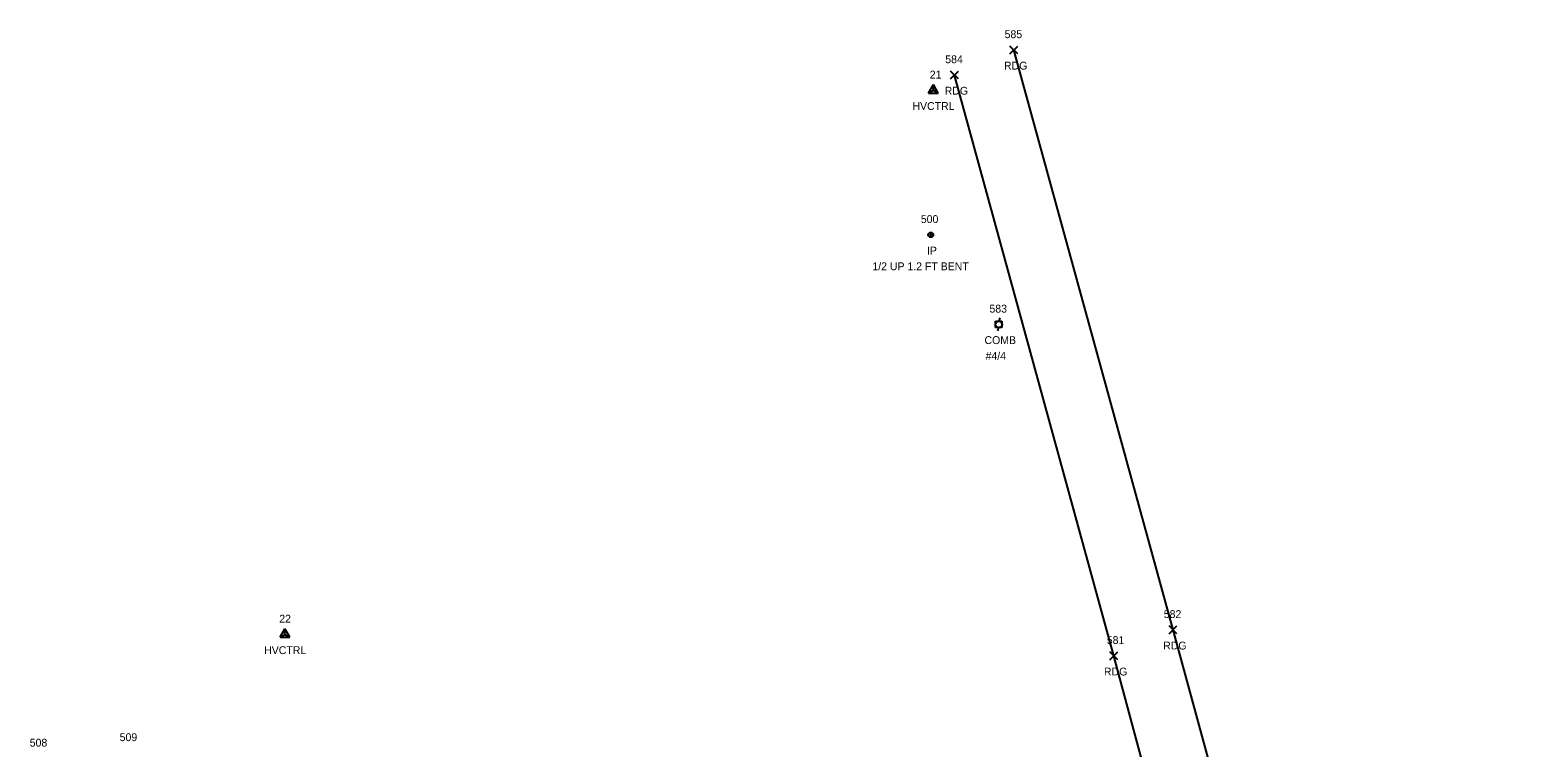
# Model space of a CAD drawing. Extents: x 1845178 to 1850791, y 714586 to 722436.
# Drawn here: x 1850338.3 to 1850721.9, y 716795.6 to 716978.2 of the extents above; entities that cross this region are included whole.
import ezdxf

# ---------------------------------------------------------------- set-up
doc = ezdxf.new("R2010")
doc.units = 0
for name, color, linetype in [('C_A', 7, 'Continuous'), ('C_I', 7, 'Continuous'), ('CPSM', 7, 'Continuous'), ('M_A', 7, 'Continuous'), ('M_C', 7, 'Continuous'), ('M_I', 7, 'Continuous'), ('MPIR', 7, 'Continuous'), ('P_A', 7, 'Continuous'), ('P_I', 7, 'Continuous'), ('P_TIC', 7, 'Continuous'), ('PEU', 7, 'Continuous'), ('R_I', 7, 'Continuous'), ('U_A', 7, 'Continuous'), ('U_C', 7, 'Continuous'), ('U_I', 7, 'Continuous'), ('UP', 7, 'Continuous')]:
    doc.layers.add(name, color=color, linetype=linetype)

msp = doc.modelspace()

# ---------------------------------------------------------------- linework, layer by layer
at = {"layer": 'CPSM'}
for p, q in [((1850566.84, 716962.13), (1850568.09, 716964.29)), ((1850566.84, 716962.13), (1850568.09, 716962.85)), ((1850569.34, 716962.13), (1850568.09, 716964.29)), ((1850568.09, 716962.85), (1850568.09, 716964.29)), ((1850568.09, 716962.85), (1850568.09, 716962.85)), ((1850568.09, 716962.85), (1850569.34, 716962.13)), ((1850566.84, 716962.13), (1850569.34, 716962.13)), ((1850401.87, 716823.71), (1850403.12, 716825.88)), ((1850401.87, 716823.71), (1850403.12, 716824.43)), ((1850404.37, 716823.71), (1850403.12, 716825.88)), ((1850403.12, 716824.43), (1850403.12, 716825.88)), ((1850403.12, 716824.43), (1850403.12, 716824.43)), ((1850403.12, 716824.43), (1850404.37, 716823.71)), ((1850401.87, 716823.71), (1850404.37, 716823.71))]:
    msp.add_line(p, q, dxfattribs=at)
at = {"layer": 'MPIR'}
for radius in [0.625, 0.0833]:
    msp.add_circle((1850567.44, 716926.08), radius, dxfattribs=at)
at = {"layer": 'P_TIC'}
for points in [[(1850587.58, 716972.12), (1850589.58, 716974.12)], [(1850589.58, 716972.12), (1850587.58, 716974.12)], [(1850572.49, 716965.74), (1850574.49, 716967.74)], [(1850574.49, 716965.74), (1850572.49, 716967.74)], [(1850628.08, 716824.6), (1850630.08, 716826.6)], [(1850630.08, 716824.6), (1850628.08, 716826.6)], [(1850613.03, 716817.99), (1850615.03, 716819.99)], [(1850615.03, 716817.99), (1850613.03, 716819.99)]]:
    msp.add_lwpolyline(points, dxfattribs=at)
at = {"layer": 'PEU'}
for points in [[(1850721.91, 716490.1), (1850702.6, 716555.29), (1850682.65, 716631.73), (1850661.37, 716707.44), (1850629.08, 716825.6), (1850588.58, 716973.12)], [(1850650.3, 716680.85), (1850644.64, 716705.31), (1850614.03, 716818.99), (1850573.49, 716966.74)]]:
    msp.add_lwpolyline(points, dxfattribs=at)
at = {"layer": 'UP'}
for p, q in [((1850584.98, 716904.97), (1850584.73, 716904.13)), ((1850583.89, 716902.47), (1850583.89, 716904.13)), ((1850583.89, 716904.13), (1850585.56, 716904.13)), ((1850585.56, 716902.47), (1850583.89, 716902.47)), ((1850584.48, 716901.63), (1850584.73, 716902.47)), ((1850584.73, 716903.3), (1850584.73, 716903.3)), ((1850585.56, 716904.13), (1850585.56, 716902.47))]:
    msp.add_line(p, q, dxfattribs=at)
msp.add_circle((1850584.73, 716903.3), 0.833, dxfattribs=at)

# ---------------------------------------------------------------- texts
at = {"layer": 'C_A'}
for p in [(1850562.78, 716957.85), (1850397.82, 716819.43)]:
    msp.add_text('HVCTRL', height=2, dxfattribs=at).set_placement(p)
at = {"layer": 'C_I'}
for s, p in [('21', (1850567.19, 716965.85)), ('22', (1850401.66, 716827.43))]:
    msp.add_text(s, height=2, dxfattribs=at).set_placement(p)
at = {"layer": 'M_A'}
msp.add_text('IP', height=2, dxfattribs=at).set_placement((1850566.48, 716921.08))
at = {"layer": 'M_C'}
msp.add_text('1/2 UP 1.2 FT BENT', height=2, dxfattribs=at).set_placement((1850552.58, 716917.08))
at = {"layer": 'M_I'}
msp.add_text('500', height=2, dxfattribs=at).set_placement((1850564.91, 716929.08))
at = {"layer": 'P_A'}
for p in [(1850586.07, 716968.12), (1850570.98, 716961.74), (1850626.57, 716820.6), (1850611.51, 716813.99)]:
    msp.add_text('RDG', height=2, dxfattribs=at).set_placement(p)
at = {"layer": 'P_I'}
for s, p in [('585', (1850586.22, 716976.12)), ('584', (1850571.13, 716969.74)), ('582', (1850626.72, 716828.6)), ('581', (1850612.23, 716821.99))]:
    msp.add_text(s, height=2, dxfattribs=at).set_placement(p)
at = {"layer": 'R_I'}
for s, p in [('508', (1850338.17, 716795.9)), ('509', (1850361.05, 716797.29))]:
    msp.add_text(s, height=2, dxfattribs=at).set_placement(p)
at = {"layer": 'U_A'}
msp.add_text('COMB', height=2, dxfattribs=at).set_placement((1850581.11, 716898.3))
at = {"layer": 'U_C'}
msp.add_text('#4/4', height=2, dxfattribs=at).set_placement((1850581.39, 716894.3))
at = {"layer": 'U_I'}
msp.add_text('583', height=2, dxfattribs=at).set_placement((1850582.37, 716906.3))

doc.saveas('drawing.dxf')
